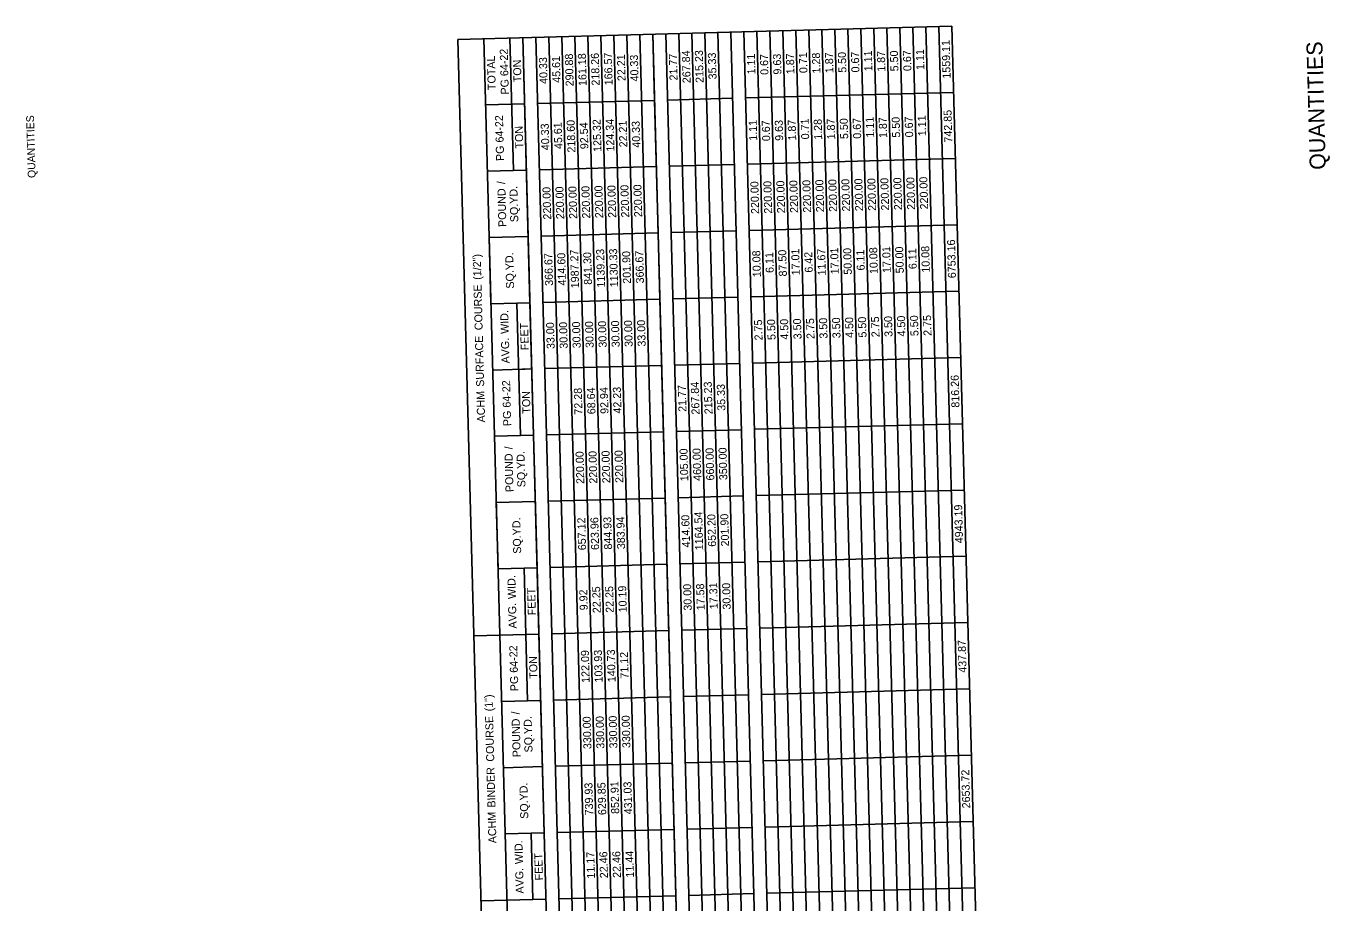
# Model space of a CAD drawing. Extents: x 1930093 to 1931323, y 596452 to 607874.
# Drawn here: x 1930161 to 1931139, y 604748 to 605406 of the extents above; entities that cross this region are included whole.
import ezdxf

# ---------------------------------------------------------------- set-up
doc = ezdxf.new("R2010")
doc.units = 0
for name, color, linetype in [('Default', 7, 'Continuous'), ('R_Border', 7, 'Continuous'), ('R_Border Prem', 7, 'Continuous')]:
    doc.layers.add(name, color=color, linetype=linetype)

msp = doc.modelspace()

# ---------------------------------------------------------------- linework, layer by layer
at = {"layer": 'Default'}
for p, q in [((1930855.36, 605405.79), (1930484.99, 605395.84)), ((1930855.36, 605405.79), (1930484.99, 605395.84)), ((1930632.52, 605350.06), (1930631.19, 605399.77)), ((1930670.88, 603921.23), (1930631.19, 605399.77)), ((1930680.63, 603921.49), (1930640.93, 605400.03)), ((1930690.37, 603921.75), (1930650.68, 605400.29)), ((1930700.12, 603922.01), (1930660.43, 605400.55)), ((1930709.86, 603922.27), (1930670.17, 605400.81)), ((1930719.61, 603922.53), (1930679.92, 605401.08)), ((1930729.36, 603922.8), (1930689.67, 605401.34)), ((1930729.36, 603922.8), (1930689.67, 605401.34)), ((1930739.1, 603923.06), (1930699.41, 605401.6)), ((1930748.85, 603923.32), (1930709.16, 605401.86)), ((1930758.6, 603923.58), (1930718.91, 605402.12)), ((1930768.34, 603923.84), (1930728.65, 605402.38)), ((1930778.09, 603924.1), (1930738.4, 605402.65)), ((1930787.84, 603924.37), (1930748.15, 605402.91)), ((1930797.58, 603924.63), (1930757.89, 605403.17)), ((1930807.33, 603924.89), (1930767.64, 605403.43)), ((1930817.08, 603925.15), (1930777.39, 605403.69)), ((1930826.82, 603925.41), (1930787.13, 605403.95)), ((1930836.57, 603925.67), (1930796.88, 605404.22)), ((1930846.32, 603925.93), (1930806.63, 605404.48)), ((1930856.06, 603926.2), (1930816.37, 605404.74)), ((1930865.81, 603926.46), (1930826.12, 605405)), ((1930875.55, 603926.72), (1930835.86, 605405.26)), ((1930885.3, 603926.98), (1930845.61, 605405.52)), ((1930895.05, 603927.24), (1930855.36, 605405.79)), ((1930524.68, 603917.3), (1930484.99, 605395.84)), ((1930533.84, 604302.81), (1930504.48, 605396.37)), ((1930526.65, 605297.48), (1930523.98, 605396.89)), ((1930573.41, 603918.61), (1930533.72, 605397.15)), ((1930539.06, 605198.32), (1930533.72, 605397.15)), ((1930583.16, 603918.87), (1930543.47, 605397.41)), ((1930592.91, 603919.13), (1930553.22, 605397.67)), ((1930602.65, 603919.39), (1930562.96, 605397.94)), ((1930612.4, 603919.66), (1930572.71, 605398.2)), ((1930622.15, 603919.92), (1930582.46, 605398.46)), ((1930631.89, 603920.18), (1930592.2, 605398.72)), ((1930641.64, 603920.44), (1930601.95, 605398.98)), ((1930651.39, 603920.7), (1930611.7, 605399.24)), ((1930661.13, 603920.96), (1930621.44, 605399.51)), ((1930691, 605351.63), (1930642.27, 605350.32)), ((1930691, 605351.63), (1930642.27, 605350.32)), ((1930856.69, 605356.08), (1930700.75, 605351.89)), ((1930856.69, 605356.08), (1930700.75, 605351.89)), ((1930535.06, 605347.44), (1930505.82, 605346.66)), ((1930632.52, 605350.06), (1930544.8, 605347.71)), ((1930632.52, 605350.06), (1930544.8, 605347.71)), ((1930635.19, 605250.65), (1930632.52, 605350.06)), ((1930692.34, 605301.92), (1930643.6, 605300.62)), ((1930692.34, 605301.92), (1930643.6, 605300.62)), ((1930858.03, 605306.37), (1930702.08, 605302.19)), ((1930858.03, 605306.37), (1930702.08, 605302.19)), ((1930536.39, 605297.74), (1930507.15, 605296.95)), ((1930633.86, 605300.35), (1930546.14, 605298)), ((1930633.86, 605300.35), (1930546.14, 605298)), ((1930859.36, 605256.66), (1930703.42, 605252.48)), ((1930859.36, 605256.66), (1930703.42, 605252.48)), ((1930537.73, 605248.03), (1930508.49, 605247.25)), ((1930509.82, 605197.54), (1930508.49, 605247.25)), ((1930635.19, 605250.65), (1930547.47, 605248.29)), ((1930635.19, 605250.65), (1930547.47, 605248.29)), ((1930636.53, 605200.94), (1930635.19, 605250.65)), ((1930693.67, 605252.22), (1930644.94, 605250.91)), ((1930693.67, 605252.22), (1930644.94, 605250.91)), ((1930860.7, 605206.96), (1930704.75, 605202.77)), ((1930860.7, 605206.96), (1930704.75, 605202.77)), ((1930539.06, 605198.32), (1930509.82, 605197.54)), ((1930539.06, 605198.32), (1930529.31, 605198.06)), ((1930531.98, 605098.65), (1930529.31, 605198.06)), ((1930544.4, 604999.49), (1930539.06, 605198.32)), ((1930636.53, 605200.94), (1930548.81, 605198.58)), ((1930636.53, 605200.94), (1930548.81, 605198.58)), ((1930648.53, 604753.58), (1930636.53, 605200.94)), ((1930695, 605202.51), (1930646.27, 605201.2)), ((1930695, 605202.51), (1930646.27, 605201.2)), ((1930862.03, 605157.25), (1930706.09, 605153.06)), ((1930862.03, 605157.25), (1930706.09, 605153.06)), ((1930540.4, 605148.62), (1930511.16, 605147.83)), ((1930540.4, 605148.62), (1930530.65, 605148.35)), ((1930637.86, 605151.23), (1930550.14, 605148.88)), ((1930637.86, 605151.23), (1930550.14, 605148.88)), ((1930696.34, 605152.8), (1930647.61, 605151.49)), ((1930696.34, 605152.8), (1930647.61, 605151.49)), ((1930863.36, 605107.54), (1930707.42, 605103.36)), ((1930863.36, 605107.54), (1930707.42, 605103.36)), ((1930541.73, 605098.91), (1930512.49, 605098.12)), ((1930639.19, 605101.53), (1930551.48, 605099.17)), ((1930639.19, 605101.53), (1930551.48, 605099.17)), ((1930697.67, 605103.1), (1930648.94, 605101.79)), ((1930697.67, 605103.1), (1930648.94, 605101.79)), ((1930864.7, 605057.84), (1930708.75, 605053.65)), ((1930864.7, 605057.84), (1930708.75, 605053.65)), ((1930543.06, 605049.2), (1930513.82, 605048.42)), ((1930515.16, 604998.71), (1930513.82, 605048.42)), ((1930640.53, 605051.82), (1930552.81, 605049.46)), ((1930640.53, 605051.82), (1930552.81, 605049.46)), ((1930699.01, 605053.39), (1930650.28, 605052.08)), ((1930699.01, 605053.39), (1930650.28, 605052.08)), ((1930544.4, 604999.49), (1930515.16, 604998.71)), ((1930544.4, 604999.49), (1930534.65, 604999.23)), ((1930537.32, 604899.82), (1930534.65, 604999.23)), ((1930549.74, 604800.67), (1930544.4, 604999.49)), ((1930641.86, 605002.11), (1930554.14, 604999.76)), ((1930641.86, 605002.11), (1930554.14, 604999.76)), ((1930700.34, 605003.68), (1930651.61, 605002.37)), ((1930700.34, 605003.68), (1930651.61, 605002.37)), ((1930866.03, 605008.13), (1930710.09, 605003.94)), ((1930866.03, 605008.13), (1930710.09, 605003.94)), ((1930643.2, 604952.4), (1930555.48, 604950.05)), ((1930643.2, 604952.4), (1930555.48, 604950.05)), ((1930701.68, 604953.97), (1930652.94, 604952.67)), ((1930701.68, 604953.97), (1930652.94, 604952.67)), ((1930867.37, 604958.42), (1930711.42, 604954.24)), ((1930867.37, 604958.42), (1930711.42, 604954.24)), ((1930545.73, 604949.79), (1930497, 604948.48)), ((1930516.49, 604949), (1930497, 604948.48)), ((1930545.73, 604949.79), (1930535.99, 604949.53)), ((1930644.53, 604902.7), (1930556.81, 604900.34)), ((1930644.53, 604902.7), (1930556.81, 604900.34)), ((1930703.01, 604904.27), (1930654.28, 604902.96)), ((1930703.01, 604904.27), (1930654.28, 604902.96)), ((1930868.7, 604908.71), (1930712.76, 604904.53)), ((1930868.7, 604908.71), (1930712.76, 604904.53)), ((1930547.07, 604900.08), (1930517.83, 604899.3)), ((1930645.87, 604852.99), (1930558.15, 604850.64)), ((1930645.87, 604852.99), (1930558.15, 604850.64)), ((1930704.35, 604854.56), (1930655.61, 604853.25)), ((1930704.35, 604854.56), (1930655.61, 604853.25)), ((1930870.04, 604859.01), (1930714.09, 604854.82)), ((1930870.04, 604859.01), (1930714.09, 604854.82)), ((1930548.4, 604850.37), (1930519.16, 604849.59)), ((1930647.2, 604803.28), (1930559.48, 604800.93)), ((1930647.2, 604803.28), (1930559.48, 604800.93)), ((1930705.68, 604804.85), (1930656.95, 604803.54)), ((1930705.68, 604804.85), (1930656.95, 604803.54)), ((1930871.37, 604809.3), (1930715.43, 604805.11)), ((1930871.37, 604809.3), (1930715.43, 604805.11)), ((1930549.74, 604800.67), (1930520.5, 604799.88)), ((1930549.74, 604800.67), (1930539.99, 604800.4)), ((1930541.32, 604750.7), (1930539.99, 604800.4)), ((1930553.74, 604651.54), (1930549.74, 604800.67)), ((1930707.01, 604755.15), (1930658.28, 604753.84)), ((1930707.01, 604755.15), (1930658.28, 604753.84)), ((1930872.7, 604759.59), (1930716.76, 604755.41)), ((1930872.7, 604759.59), (1930716.76, 604755.41)), ((1930551.07, 604750.96), (1930502.34, 604749.65)), ((1930648.53, 604753.58), (1930560.82, 604751.22)), ((1930648.53, 604753.58), (1930560.82, 604751.22)), ((1930652.54, 604604.45), (1930648.53, 604753.58))]:
    msp.add_line(p, q, dxfattribs=at)

# ---------------------------------------------------------------- texts
for s, p in [('1559.11', (1930854.54, 605366.42)), ('TOTAL', (1930513.4, 605357.88)), (' 64-22', (1930522.93, 605366.12)), ('40.33', (1930552.29, 605362.48)), ('45.61', (1930562.02, 605363.32)), ('290.88', (1930571.84, 605360.67)), ('161.18', (1930581.59, 605360.93)), ('218.26', (1930591.33, 605361.2)), ('166.57', (1930601.08, 605361.46)), ('22.21', (1930610.75, 605364.63)), ('40.33', (1930620.51, 605364.31)), ('21.77', (1930649.75, 605365.1)), ('267.84', (1930659.56, 605363.04)), ('215.23', (1930669.31, 605363.29)), ('35.33', (1930678.99, 605365.88)), ('1.11', (1930708.15, 605369.58)), ('0.67', (1930717.91, 605369.26)), ('9.63', (1930727.66, 605369.52)), ('1.87', (1930737.41, 605369.78)), ('0.71', (1930747.14, 605370.62)), ('1.28', (1930756.9, 605370.3)), ('1.87', (1930766.65, 605370.57)), ('5.50', (1930776.39, 605370.84)), ('0.67', (1930786.14, 605371.09)), ('1.11', (1930795.87, 605371.93)), ('1.87', (1930805.63, 605371.61)), ('5.50', (1930815.38, 605371.89)), ('0.67', (1930825.12, 605372.14)), ('1.11', (1930834.86, 605372.98)), ('TON', (1930532.74, 605363.74)), ('PG', (1930523.24, 605354.52)), ('742.85', (1930855.83, 605318.49)), (' 64-22', (1930519.39, 605316.29)), ('40.33', (1930553.62, 605312.77)), ('45.61', (1930563.35, 605313.62)), ('218.60', (1930573.18, 605310.98)), ('92.54', (1930582.86, 605313.57)), ('125.32', (1930592.67, 605311.52)), ('124.34', (1930602.41, 605311.77)), ('22.21', (1930612.08, 605314.92)), ('40.33', (1930621.85, 605314.6)), ('1.11', (1930709.49, 605319.87)), ('0.67', (1930719.25, 605319.55)), ('9.63', (1930728.99, 605319.81)), ('1.87', (1930738.74, 605320.07)), ('0.71', (1930748.47, 605320.92)), ('1.28', (1930758.23, 605320.59)), ('1.87', (1930767.98, 605320.86)), ('5.50', (1930777.73, 605321.13)), ('0.67', (1930787.47, 605321.38)), ('1.11', (1930797.2, 605322.22)), ('1.87', (1930806.97, 605321.9)), ('5.50', (1930816.71, 605322.18)), ('0.67', (1930826.46, 605322.43)), ('1.11', (1930836.19, 605323.27)), ('TON', (1930534.08, 605314.03)), ('PG', (1930519.7, 605304.68)), ('220.00', (1930827.92, 605268.07)), ('220.00', (1930837.66, 605268.34)), (' /', (1930520.6, 605285.05)), ('POUND', (1930521.4, 605255.19)), ('SQ.YD.', (1930530.31, 605258.78)), ('220.00', (1930555.02, 605260.75)), ('220.00', (1930564.76, 605261.01)), ('220.00', (1930574.51, 605261.27)), ('220.00', (1930584.26, 605261.53)), ('220.00', (1930594, 605261.79)), ('220.00', (1930603.75, 605262.06)), ('220.00', (1930613.5, 605262.32)), ('220.00', (1930623.24, 605262.58)), ('220.00', (1930710.96, 605264.93)), ('220.00', (1930720.71, 605265.2)), ('220.00', (1930730.45, 605265.46)), ('220.00', (1930740.2, 605265.72)), ('220.00', (1930749.95, 605265.98)), ('220.00', (1930759.69, 605266.24)), ('220.00', (1930769.44, 605266.5)), ('220.00', (1930779.19, 605266.77)), ('220.00', (1930788.93, 605267.03)), ('220.00', (1930798.68, 605267.29)), ('220.00', (1930808.43, 605267.55)), ('220.00', (1930818.17, 605267.81)), ('6753.16', (1930858.56, 605216.77)), (' (1/2")', (1930502.65, 605213.33)), ('SQ.YD.', (1930527.15, 605208.95)), ('366.67', (1930556.35, 605211.03)), ('414.60', (1930566.1, 605211.3)), ('1987.27', (1930575.91, 605209.22)), ('841.30', (1930585.59, 605211.83)), ('1139.23', (1930595.4, 605209.75)), ('1130.33', (1930605.15, 605210.01)), ('201.90', (1930614.83, 605212.61)), ('366.67', (1930624.58, 605212.86)), ('10.08', (1930712.23, 605217.54)), ('6.11', (1930721.9, 605220.72)), ('87.50', (1930731.73, 605218.08)), ('17.01', (1930741.46, 605218.91)), ('6.42', (1930751.16, 605220.95)), ('11.67', (1930760.96, 605218.85)), ('17.01', (1930770.7, 605219.7)), ('50.00', (1930780.46, 605219.39)), ('6.11', (1930790.13, 605222.55)), ('10.08', (1930799.95, 605219.9)), ('17.01', (1930809.68, 605220.74)), ('50.00', (1930819.44, 605220.43)), ('6.11', (1930829.11, 605223.59)), ('10.08', (1930838.94, 605220.94)), (' COURSE', (1930503.66, 605175.56)), (' WID.', (1930523.24, 605172.8)), ('30.00', (1930606.36, 605164.97)), ('30.00', (1930616.1, 605165.23)), ('33.00', (1930625.85, 605165.49)), ('2.75', (1930713.5, 605170.14)), ('5.50', (1930723.25, 605170.44)), ('4.50', (1930733, 605170.7)), ('3.50', (1930742.74, 605170.96)), ('2.75', (1930752.49, 605171.19)), ('3.50', (1930762.24, 605171.49)), ('3.50', (1930771.98, 605171.75)), ('4.50', (1930781.73, 605172.01)), ('5.50', (1930791.48, 605172.27)), ('2.75', (1930801.22, 605172.5)), ('3.50', (1930810.97, 605172.8)), ('4.50', (1930820.72, 605173.06)), ('5.50', (1930830.46, 605173.32)), ('2.75', (1930840.21, 605173.55)), ('FEET', (1930538.14, 605162.79)), ('33.00', (1930557.62, 605163.66)), ('30.00', (1930567.37, 605163.92)), ('30.00', (1930577.12, 605164.19)), ('30.00', (1930586.86, 605164.45)), ('30.00', (1930596.61, 605164.71)), (' SURFACE', (1930504.8, 605133.13)), ('AVG.', (1930523.77, 605152.89)), (' 64-22', (1930524.73, 605117.46)), ('21.77', (1930656.42, 605116.56)), ('267.84', (1930666.23, 605114.51)), ('215.23', (1930675.98, 605114.76)), ('35.33', (1930685.66, 605117.35)), ('816.26', (1930861.16, 605119.69)), ('ACHM', (1930505.46, 605108.59)), ('TON', (1930539.42, 605115.2)), ('72.28', (1930578.45, 605114.46)), ('68.64', (1930588.2, 605114.74)), ('92.94', (1930597.94, 605115.01)), ('42.23', (1930607.69, 605115.25)), ('PG', (1930525.04, 605105.85)), (' /', (1930525.94, 605086.22)), ('220.00', (1930589.59, 605062.7)), ('220.00', (1930599.34, 605062.97)), ('220.00', (1930609.09, 605063.23)), ('105.00', (1930657.82, 605064.54)), ('460.00', (1930667.57, 605064.8)), ('660.00', (1930677.31, 605065.06)), ('350.00', (1930687.06, 605065.32)), ('POUND', (1930526.74, 605056.37)), ('SQ.YD.', (1930535.65, 605059.95)), ('220.00', (1930579.85, 605062.44)), ('414.60', (1930659.15, 605014.83)), ('1164.54', (1930668.96, 605012.76)), ('652.20', (1930678.65, 605015.35)), ('201.90', (1930688.39, 605015.61)), ('4943.19', (1930863.89, 605017.99)), ('SQ.YD.', (1930532.48, 605010.12)), ('657.12', (1930581.18, 605012.76)), ('623.96', (1930590.93, 605012.99)), ('844.93', (1930600.67, 605013.25)), ('383.94', (1930610.42, 605013.52)), (' WID.', (1930528.58, 604973.97)), ('FEET', (1930543.48, 604963.97)), ('9.92', (1930582.39, 604967.71)), ('22.25', (1930592.2, 604965.59)), ('22.25', (1930601.95, 604965.85)), ('10.19', (1930611.69, 604966.13)), ('30.00', (1930660.42, 604967.45)), ('17.58', (1930670.17, 604967.7)), ('17.31', (1930679.9, 604968.54)), ('30.00', (1930689.66, 604968.24)), ('AVG.', (1930529.11, 604954.06)), (' 64-22', (1930530.06, 604918.63)), ('437.87', (1930866.5, 604920.89)), ('TON', (1930544.75, 604916.37)), ('122.09', (1930583.85, 604913.31)), ('103.93', (1930593.6, 604913.57)), ('140.73', (1930603.34, 604913.83)), ('71.12', (1930613.03, 604916.46)), ('PG', (1930530.37, 604907.03)), (' (1")', (1930511.33, 604889.72)), (' /', (1930531.28, 604887.39)), (' COURSE', (1930512.35, 604851.95)), ('POUND', (1930532.08, 604857.54)), ('SQ.YD.', (1930540.99, 604861.12)), ('330.00', (1930585.18, 604863.61)), ('330.00', (1930594.93, 604863.88)), ('330.00', (1930604.68, 604864.14)), ('330.00', (1930614.42, 604864.4)), (' BINDER', (1930513.27, 604817.53)), ('2653.72', (1930869.23, 604819.18)), ('SQ.YD.', (1930537.82, 604811.29)), ('739.93', (1930586.52, 604813.9)), ('629.85', (1930596.27, 604814.14)), ('852.91', (1930606, 604815)), ('431.03', (1930615.76, 604814.68)), ('ACHM', (1930513.93, 604792.99)), (' WID.', (1930533.91, 604775.14)), ('FEET', (1930548.81, 604765.14)), ('11.17', (1930587.79, 604766.52)), ('22.46', (1930597.54, 604766.78)), ('22.46', (1930607.28, 604767.04)), ('11.44', (1930617.03, 604767.32)), ('AVG.', (1930534.45, 604755.23))]:
    msp.add_text(s, height=6, rotation=91.53769, dxfattribs=at).set_placement(p)
at = {"layer": 'R_Border'}
msp.add_text('QUANTITIES', height=12, rotation=91.53769, dxfattribs=at).set_placement((1931135.88, 605298.16))
at = {"layer": 'R_Border Prem'}
msp.add_text('QUANTITIES', height=5.862, rotation=91.53769, dxfattribs=at).set_placement((1930168.33, 605291.91))

doc.saveas('drawing.dxf')
